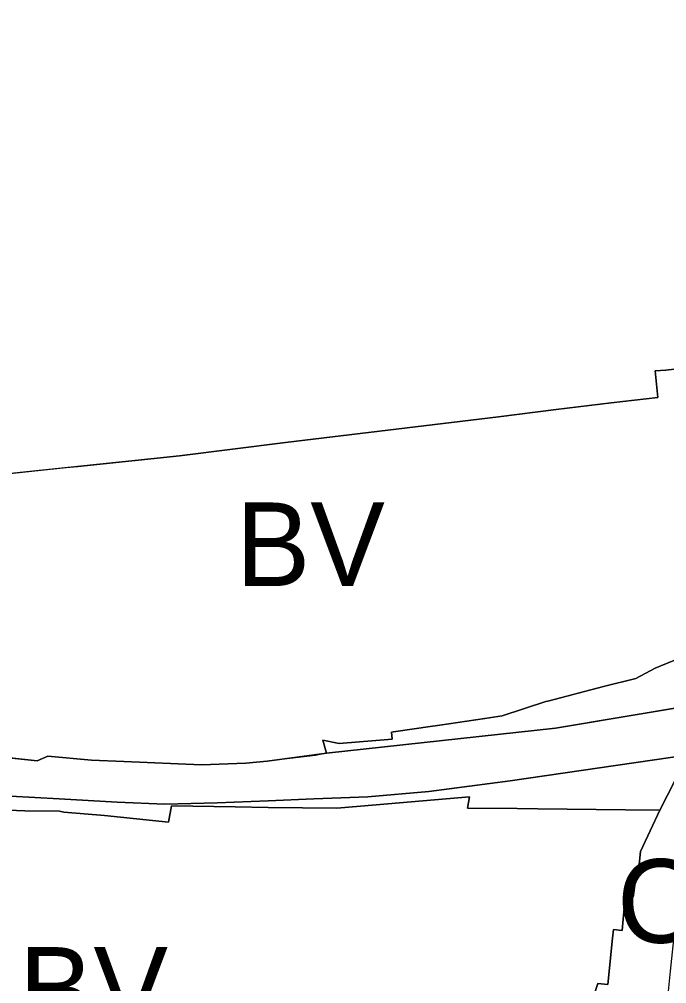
# Model space of a CAD drawing. Extents: x -555509 to -553005, y -1186756 to -1182560.
# Drawn here: x -554751 to -554642.6, y -1184542.3 to -1184380.7 of the extents above; entities that cross this region are included whole.
import ezdxf

# ---------------------------------------------------------------- set-up
doc = ezdxf.new("R2010")
doc.units = 0
for name, color, linetype in [('Level 15', 7, 'Continuous'), ('Level 36', 7, 'Continuous'), ('Level 52', 7, 'Continuous'), ('Level 59', 7, 'Continuous'), ('Level 6', 7, 'Continuous'), ('OBRYS_PLOCH', 7, 'Continuous'), ('stav_BV', 7, 'Continuous'), ('stav_DS', 7, 'Continuous'), ('stav_PU', 7, 'Continuous'), ('stav_ZZ', 7, 'Continuous')]:
    doc.layers.add(name, color=color, linetype=linetype)

msp = doc.modelspace()

# ---------------------------------------------------------------- linework, layer by layer
at = {"layer": 'Level 15'}
for points in [[(-554639.21, -1184487.21), (-554644.53, -1184489.39), (-554647.72, -1184491.13), (-554653.14, -1184492.49), (-554662.48, -1184494.93), (-554662.81, -1184495.02), (-554670.13, -1184497.41), (-554671.59, -1184497.63), (-554673.04, -1184497.85), (-554680.58, -1184498.95), (-554680.98, -1184499.02), (-554682.18, -1184499.2), (-554687.98, -1184500.03), (-554688.33, -1184500.08), (-554688.68, -1184500.13), (-554688.57, -1184501.33), (-554697.44, -1184502.04), (-554700.16, -1184501.46), (-554699.57, -1184503.65), (-554699.57, -1184503.65), (-554661.22, -1184499.44), (-554615.47, -1184491.83)], [(-554746.28, -1184504.15), (-554747.17, -1184504.55), (-554748.06, -1184504.95), (-554757.52, -1184503.92), (-554766.86, -1184501.55), (-554772.36, -1184500.16), (-554791.66, -1184494.22), (-554798.98, -1184492.03), (-554805.45, -1184490.44), (-554806.7, -1184490.13), (-554807.73, -1184488.86)], [(-554593.44, -1184495.14), (-554615.47, -1184491.83), (-554661.22, -1184499.44)], [(-554661.22, -1184499.44), (-554699.57, -1184503.65), (-554699.57, -1184503.65)], [(-554699.57, -1184503.65), (-554709.5, -1184504.98), (-554713.07, -1184505.34)], [(-554738.96, -1184504.8), (-554746.28, -1184504.15)], [(-554733.5, -1184505.03), (-554738.96, -1184504.8)], [(-554713.07, -1184505.34), (-554713.07, -1184505.34), (-554720.52, -1184505.59), (-554733.5, -1184505.03)], [(-554642.43, -1184545.2), (-554641.91, -1184540.17), (-554640.14, -1184523.18), (-554639.47, -1184516.74), (-554637.02, -1184517), (-554630.53, -1184504.15), (-554639.95, -1184505.76), (-554643.74, -1184513.22), (-554646.97, -1184520.1), (-554647.28, -1184523.42), (-554647.58, -1184523.38), (-554648.22, -1184527.77), (-554649.54, -1184527.64), (-554650.06, -1184533.35), (-554651.5, -1184533.21), (-554651.65, -1184534.63), (-554652.44, -1184542.42), (-554654.14, -1184542.26), (-554661.63, -1184565.18)], [(-554643.74, -1184513.22), (-554639.95, -1184505.76), (-554630.53, -1184504.15)], [(-554709.32, -1184512.75), (-554697.83, -1184512.89), (-554691.23, -1184512.32), (-554675.6, -1184510.96), (-554675.96, -1184512.84), (-554667.63, -1184512.94), (-554664.16, -1184512.99), (-554664.16, -1184512.99)], [(-554757.41, -1184512.9), (-554754.4, -1184513.13), (-554750.1, -1184513.32), (-554744.31, -1184513.39), (-554743.58, -1184513.52), (-554736.79, -1184514.11), (-554726.04, -1184515.23)], [(-554726.04, -1184515.23), (-554725.56, -1184512.5), (-554714.9, -1184512.64), (-554709.32, -1184512.75)], [(-554664.16, -1184512.99), (-554649.5, -1184513.16), (-554643.74, -1184513.22)]]:
    msp.add_lwpolyline(points, dxfattribs=at)
at = {"layer": 'Level 36'}
msp.add_lwpolyline([(-554639.28, -1184439.13), (-554639.94, -1184439.16), (-554642.71, -1184439.5), (-554644.5, -1184439.63), (-554644.06, -1184444.05), (-554651.87, -1184444.95), (-554661.09, -1184446.08), (-554670.78, -1184447.34), (-554706.42, -1184451.63), (-554724.18, -1184453.83), (-554788.3, -1184460.55)], dxfattribs=at)
at = {"layer": 'Level 52'}
msp.add_lwpolyline([(-554637.47, -1184365.6), (-554639.28, -1184381.15), (-554638.44, -1184403.84), (-554637.94, -1184420.98), (-554635.54, -1184438.95), (-554639.94, -1184439.16), (-554642.71, -1184439.5), (-554644.5, -1184439.63), (-554644.06, -1184444.05), (-554651.87, -1184444.95), (-554661.09, -1184446.08), (-554670.78, -1184447.34), (-554706.42, -1184451.63), (-554724.18, -1184453.83), (-554788.3, -1184460.55)], dxfattribs=at)
at = {"layer": 'Level 6'}
msp.add_lwpolyline([(-554639.14, -1184384.89), (-554638.44, -1184403.84), (-554637.94, -1184420.98), (-554635.54, -1184438.95), (-554639.94, -1184439.16), (-554642.71, -1184439.5), (-554644.5, -1184439.63), (-554644.06, -1184444.05), (-554651.87, -1184444.95), (-554661.09, -1184446.08), (-554670.78, -1184447.34), (-554706.42, -1184451.63), (-554724.18, -1184453.83), (-554788.3, -1184460.55)], dxfattribs=at)
at = {"layer": 'OBRYS_PLOCH'}
for p, q in [((-554644.5, -1184439.63), (-554642.71, -1184439.5)), ((-554706.42, -1184451.63), (-554670.78, -1184447.34)), ((-554670.78, -1184447.34), (-554661.09, -1184446.08)), ((-554724.18, -1184453.83), (-554706.42, -1184451.63)), ((-554741.22, -1184455.62), (-554724.18, -1184453.83)), ((-554755.79, -1184457.14), (-554743.17, -1184455.82)), ((-554743.17, -1184455.82), (-554741.22, -1184455.62)), ((-554615.47, -1184491.83), (-554661.22, -1184499.44)), ((-554661.22, -1184499.44), (-554699.57, -1184503.65)), ((-554699.57, -1184503.65), (-554701.44, -1184504.04)), ((-554668.82, -1184508.29), (-554638.17, -1184503.82)), ((-554638.17, -1184503.82), (-554668.82, -1184508.29)), ((-554746.28, -1184504.15), (-554747.17, -1184504.55)), ((-554738.96, -1184504.8), (-554746.28, -1184504.15)), ((-554733.5, -1184505.03), (-554738.96, -1184504.8)), ((-554720.52, -1184505.59), (-554733.5, -1184505.03)), ((-554713.07, -1184505.34), (-554720.52, -1184505.59)), ((-554709.5, -1184504.98), (-554713.07, -1184505.34)), ((-554701.44, -1184504.04), (-554709.5, -1184504.98)), ((-554682.41, -1184510.08), (-554668.82, -1184508.29)), ((-554668.82, -1184508.29), (-554682.41, -1184510.08)), ((-554692.65, -1184510.98), (-554682.41, -1184510.08)), ((-554682.41, -1184510.08), (-554692.65, -1184510.98)), ((-554752.52, -1184510.88), (-554744.35, -1184511.28)), ((-554744.35, -1184511.28), (-554752.52, -1184510.88)), ((-554744.35, -1184511.28), (-554734.66, -1184511.87)), ((-554734.66, -1184511.87), (-554744.35, -1184511.28)), ((-554734.66, -1184511.87), (-554726.63, -1184512.18)), ((-554726.63, -1184512.18), (-554734.66, -1184511.87)), ((-554726.63, -1184512.18), (-554717.9, -1184511.99)), ((-554717.9, -1184511.99), (-554726.63, -1184512.18)), ((-554717.9, -1184511.99), (-554709.32, -1184511.66)), ((-554709.32, -1184511.66), (-554717.9, -1184511.99)), ((-554709.32, -1184511.66), (-554701.67, -1184511.31)), ((-554701.67, -1184511.31), (-554709.32, -1184511.66)), ((-554701.67, -1184511.31), (-554692.65, -1184510.98)), ((-554692.65, -1184510.98), (-554701.67, -1184511.31)), ((-554646.97, -1184520.1), (-554643.74, -1184513.22))]:
    msp.add_line(p, q, dxfattribs=at)
for points in [[(-554639.28, -1184381.15), (-554638.44, -1184403.84), (-554637.94, -1184420.98), (-554635.54, -1184438.95), (-554639.94, -1184439.16), (-554642.71, -1184439.5), (-554644.5, -1184439.63), (-554644.06, -1184444.05), (-554651.87, -1184444.95), (-554661.09, -1184446.08), (-554670.78, -1184447.34), (-554706.42, -1184451.63), (-554724.18, -1184453.83), (-554788.3, -1184460.55)], [(-554642.71, -1184439.5), (-554639.94, -1184439.16), (-554635.54, -1184438.95)], [(-554661.09, -1184446.08), (-554651.87, -1184444.95), (-554644.06, -1184444.05), (-554644.5, -1184439.63)], [(-554647.72, -1184491.13), (-554644.53, -1184489.39), (-554639.21, -1184487.21), (-554637.44, -1184486.54), (-554637.86, -1184484.85), (-554635.23, -1184483.3), (-554629.92, -1184480.1), (-554622.43, -1184475.36)], [(-554662.48, -1184494.93), (-554653.14, -1184492.49), (-554647.72, -1184491.13)], [(-554688.68, -1184500.13), (-554688.33, -1184500.08), (-554687.98, -1184500.03), (-554682.18, -1184499.2), (-554680.98, -1184499.02), (-554680.58, -1184498.95), (-554673.04, -1184497.85), (-554671.59, -1184497.63), (-554670.13, -1184497.41), (-554662.81, -1184495.02), (-554662.48, -1184494.93)], [(-554772.36, -1184500.16), (-554766.86, -1184501.55), (-554757.52, -1184503.92), (-554748.06, -1184504.95), (-554747.17, -1184504.55), (-554746.28, -1184504.15)], [(-554699.57, -1184503.65), (-554700.16, -1184501.46), (-554697.44, -1184502.04), (-554688.57, -1184501.33), (-554688.68, -1184500.13)], [(-554747.17, -1184504.55), (-554748.06, -1184504.95), (-554757.24, -1184503.95)], [(-554713.07, -1184505.34), (-554709.5, -1184504.98), (-554699.57, -1184503.65)], [(-554746.28, -1184504.15), (-554738.96, -1184504.8), (-554733.5, -1184505.03)], [(-554733.5, -1184505.03), (-554720.52, -1184505.59), (-554713.07, -1184505.34)], [(-554664.16, -1184512.99), (-554667.63, -1184512.94), (-554675.96, -1184512.84), (-554675.6, -1184510.96), (-554691.23, -1184512.32), (-554697.83, -1184512.89), (-554709.32, -1184512.75)], [(-554709.32, -1184512.75), (-554697.83, -1184512.89), (-554691.23, -1184512.32), (-554675.6, -1184510.96), (-554675.96, -1184512.84), (-554667.63, -1184512.94), (-554664.16, -1184512.99)], [(-554726.04, -1184515.23), (-554736.79, -1184514.11), (-554743.58, -1184513.52), (-554744.31, -1184513.39), (-554750.1, -1184513.32), (-554754.4, -1184513.13), (-554757.41, -1184512.9)], [(-554757.41, -1184512.9), (-554754.4, -1184513.13), (-554750.1, -1184513.32), (-554744.31, -1184513.39), (-554743.58, -1184513.52), (-554736.79, -1184514.11), (-554726.04, -1184515.23)], [(-554709.32, -1184512.75), (-554714.9, -1184512.64), (-554725.56, -1184512.5), (-554726.04, -1184515.23)], [(-554726.04, -1184515.23), (-554725.56, -1184512.5), (-554714.9, -1184512.64), (-554709.32, -1184512.75)], [(-554643.74, -1184513.22), (-554646.97, -1184520.1), (-554647.28, -1184523.42), (-554647.58, -1184523.38), (-554648.22, -1184527.77), (-554649.54, -1184527.64), (-554650.06, -1184533.35), (-554651.5, -1184533.21), (-554651.65, -1184534.63), (-554652.44, -1184542.42), (-554654.14, -1184542.26), (-554661.63, -1184565.18), (-554665.78, -1184591.72), (-554668.37, -1184620.38), (-554675.11, -1184635.77), (-554684.77, -1184643.87), (-554693.15, -1184668.37)], [(-554643.74, -1184513.22), (-554649.5, -1184513.16), (-554664.16, -1184512.99)], [(-554664.16, -1184512.99), (-554649.5, -1184513.16), (-554643.74, -1184513.22)], [(-554664.62, -1184584.28), (-554661.63, -1184565.18), (-554654.14, -1184542.26), (-554652.44, -1184542.42), (-554651.65, -1184534.63), (-554651.5, -1184533.21), (-554650.06, -1184533.35), (-554649.54, -1184527.64), (-554648.22, -1184527.77), (-554647.58, -1184523.38), (-554647.28, -1184523.42), (-554646.97, -1184520.1)]]:
    msp.add_lwpolyline(points, dxfattribs=at)
at = {"layer": 'stav_BV'}
msp.add_line((-554646.97, -1184520.1), (-554643.74, -1184513.22), dxfattribs=at)
for points in [[(-554639.28, -1184381.15), (-554638.44, -1184403.84), (-554637.94, -1184420.98), (-554635.54, -1184438.95), (-554639.94, -1184439.16), (-554642.71, -1184439.5), (-554644.5, -1184439.63), (-554644.06, -1184444.05), (-554651.87, -1184444.95), (-554661.09, -1184446.08), (-554670.78, -1184447.34), (-554706.42, -1184451.63), (-554724.18, -1184453.83), (-554788.3, -1184460.55)], [(-554647.72, -1184491.13), (-554644.53, -1184489.39), (-554639.21, -1184487.21), (-554637.44, -1184486.54), (-554637.86, -1184484.85), (-554635.23, -1184483.3), (-554629.92, -1184480.1), (-554622.43, -1184475.36)], [(-554662.48, -1184494.93), (-554653.14, -1184492.49), (-554647.72, -1184491.13)], [(-554688.68, -1184500.13), (-554688.33, -1184500.08), (-554687.98, -1184500.03), (-554682.18, -1184499.2), (-554680.98, -1184499.02), (-554680.58, -1184498.95), (-554673.04, -1184497.85), (-554671.59, -1184497.63), (-554670.13, -1184497.41), (-554662.81, -1184495.02), (-554662.48, -1184494.93)], [(-554772.36, -1184500.16), (-554766.86, -1184501.55), (-554757.52, -1184503.92), (-554748.06, -1184504.95), (-554747.17, -1184504.55), (-554746.28, -1184504.15)], [(-554699.57, -1184503.65), (-554700.16, -1184501.46), (-554697.44, -1184502.04), (-554688.57, -1184501.33), (-554688.68, -1184500.13)], [(-554713.07, -1184505.34), (-554709.5, -1184504.98), (-554699.57, -1184503.65)], [(-554746.28, -1184504.15), (-554738.96, -1184504.8), (-554733.5, -1184505.03)], [(-554733.5, -1184505.03), (-554720.52, -1184505.59), (-554713.07, -1184505.34)], [(-554664.16, -1184512.99), (-554667.63, -1184512.94), (-554675.96, -1184512.84), (-554675.6, -1184510.96), (-554691.23, -1184512.32), (-554697.83, -1184512.89), (-554709.32, -1184512.75)], [(-554726.04, -1184515.23), (-554736.79, -1184514.11), (-554743.58, -1184513.52), (-554744.31, -1184513.39), (-554750.1, -1184513.32), (-554754.4, -1184513.13), (-554757.41, -1184512.9)], [(-554709.32, -1184512.75), (-554714.9, -1184512.64), (-554725.56, -1184512.5), (-554726.04, -1184515.23)], [(-554643.74, -1184513.22), (-554649.5, -1184513.16), (-554664.16, -1184512.99)], [(-554664.62, -1184584.28), (-554661.63, -1184565.18), (-554654.14, -1184542.26), (-554652.44, -1184542.42), (-554651.65, -1184534.63), (-554651.5, -1184533.21), (-554650.06, -1184533.35), (-554649.54, -1184527.64), (-554648.22, -1184527.77), (-554647.58, -1184523.38), (-554647.28, -1184523.42), (-554646.97, -1184520.1)]]:
    msp.add_lwpolyline(points, dxfattribs=at)
at = {"layer": 'stav_DS'}
for p, q in [((-554615.47, -1184491.83), (-554661.22, -1184499.44)), ((-554661.22, -1184499.44), (-554699.57, -1184503.65)), ((-554699.57, -1184503.65), (-554701.44, -1184504.04)), ((-554668.82, -1184508.29), (-554638.17, -1184503.82)), ((-554746.28, -1184504.15), (-554747.17, -1184504.55)), ((-554720.52, -1184505.59), (-554733.5, -1184505.03)), ((-554713.07, -1184505.34), (-554720.52, -1184505.59)), ((-554709.5, -1184504.98), (-554713.07, -1184505.34)), ((-554701.44, -1184504.04), (-554709.5, -1184504.98)), ((-554682.41, -1184510.08), (-554668.82, -1184508.29)), ((-554692.65, -1184510.98), (-554682.41, -1184510.08)), ((-554752.52, -1184510.88), (-554744.35, -1184511.28)), ((-554744.35, -1184511.28), (-554734.66, -1184511.87)), ((-554734.66, -1184511.87), (-554726.63, -1184512.18)), ((-554726.63, -1184512.18), (-554717.9, -1184511.99)), ((-554717.9, -1184511.99), (-554709.32, -1184511.66)), ((-554709.32, -1184511.66), (-554701.67, -1184511.31)), ((-554701.67, -1184511.31), (-554692.65, -1184510.98))]:
    msp.add_line(p, q, dxfattribs=at)
for points in [[(-554747.17, -1184504.55), (-554748.06, -1184504.95), (-554757.24, -1184503.95)], [(-554733.5, -1184505.03), (-554738.96, -1184504.8), (-554746.28, -1184504.15)]]:
    msp.add_lwpolyline(points, dxfattribs=at)
at = {"layer": 'stav_PU'}
for p, q in [((-554738.96, -1184504.8), (-554746.28, -1184504.15)), ((-554733.5, -1184505.03), (-554738.96, -1184504.8))]:
    msp.add_line(p, q, dxfattribs=at)
for points in [[(-554639.21, -1184487.21), (-554644.53, -1184489.39), (-554647.72, -1184491.13), (-554653.14, -1184492.49), (-554662.48, -1184494.93), (-554662.81, -1184495.02), (-554670.13, -1184497.41), (-554671.59, -1184497.63), (-554673.04, -1184497.85), (-554680.58, -1184498.95), (-554680.98, -1184499.02), (-554682.18, -1184499.2), (-554687.98, -1184500.03), (-554688.33, -1184500.08), (-554688.68, -1184500.13), (-554688.57, -1184501.33), (-554697.44, -1184502.04), (-554700.16, -1184501.46), (-554699.57, -1184503.65)], [(-554746.28, -1184504.15), (-554747.17, -1184504.55), (-554748.06, -1184504.95), (-554757.52, -1184503.92), (-554766.86, -1184501.55), (-554772.36, -1184500.16), (-554791.66, -1184494.22), (-554798.98, -1184492.03), (-554805.45, -1184490.44), (-554806.7, -1184490.13), (-554807.73, -1184488.86)], [(-554699.57, -1184503.65), (-554709.5, -1184504.98), (-554713.07, -1184505.34)], [(-554713.07, -1184505.34), (-554720.52, -1184505.59), (-554733.5, -1184505.03)], [(-554709.32, -1184512.75), (-554697.83, -1184512.89), (-554691.23, -1184512.32), (-554675.6, -1184510.96), (-554675.96, -1184512.84), (-554667.63, -1184512.94), (-554664.16, -1184512.99)], [(-554757.41, -1184512.9), (-554754.4, -1184513.13), (-554750.1, -1184513.32), (-554744.31, -1184513.39), (-554743.58, -1184513.52), (-554736.79, -1184514.11), (-554726.04, -1184515.23)], [(-554726.04, -1184515.23), (-554725.56, -1184512.5), (-554714.9, -1184512.64), (-554709.32, -1184512.75)], [(-554643.74, -1184513.22), (-554646.97, -1184520.1), (-554647.28, -1184523.42), (-554647.58, -1184523.38), (-554648.22, -1184527.77), (-554649.54, -1184527.64), (-554650.06, -1184533.35), (-554651.5, -1184533.21), (-554651.65, -1184534.63), (-554652.44, -1184542.42), (-554654.14, -1184542.26), (-554661.63, -1184565.18), (-554665.78, -1184591.72), (-554668.37, -1184620.38), (-554675.11, -1184635.77), (-554684.77, -1184643.87), (-554693.15, -1184668.37)], [(-554664.16, -1184512.99), (-554649.5, -1184513.16), (-554643.74, -1184513.22)]]:
    msp.add_lwpolyline(points, dxfattribs=at)
at = {"layer": 'stav_ZZ'}
for p, q in [((-554642.71, -1184439.5), (-554639.94, -1184439.16)), ((-554644.5, -1184439.63), (-554642.71, -1184439.5)), ((-554644.06, -1184444.05), (-554644.5, -1184439.63)), ((-554651.87, -1184444.95), (-554644.06, -1184444.05)), ((-554661.09, -1184446.08), (-554651.87, -1184444.95)), ((-554706.42, -1184451.63), (-554670.78, -1184447.34)), ((-554670.78, -1184447.34), (-554661.09, -1184446.08)), ((-554724.18, -1184453.83), (-554706.42, -1184451.63)), ((-554741.22, -1184455.62), (-554724.18, -1184453.83)), ((-554755.79, -1184457.14), (-554743.17, -1184455.82)), ((-554743.17, -1184455.82), (-554741.22, -1184455.62))]:
    msp.add_line(p, q, dxfattribs=at)

# ---------------------------------------------------------------- texts
at = {"layer": 'Level 59'}
for s, p in [('BV', (-554714.77, -1184475.66)), ('OK', (-554650.84, -1184535.41)), ('BV', (-554751.1, -1184550.13))]:
    msp.add_text(s, height=14, dxfattribs=at).set_placement(p)

doc.saveas('drawing.dxf')
